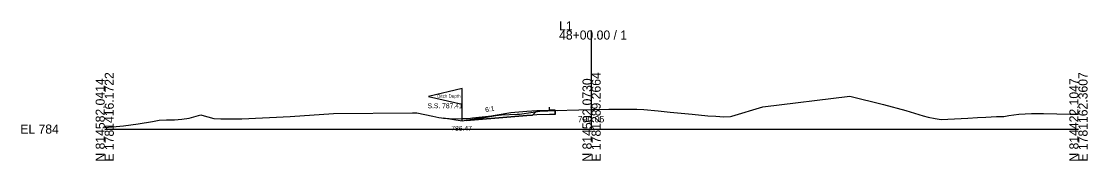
# Model space of a CAD drawing. Extents: x 5574 to 10203, y -10 to 9546.
# Drawn here: x 5574.3 to 5902.8, y 4990.3 to 5033.1 of the extents above; entities that cross this region are included whole.
import ezdxf

# ---------------------------------------------------------------- set-up
doc = ezdxf.new("R2010")
doc.units = 0
for name, color, linetype in [('Exist Cross Section Cell', 7, 'Continuous'), ('Exist XS Center Line Elevation Label', 7, 'Continuous'), ('Exist XS Ground Line', 7, 'Continuous'), ('Prop XS Ditch Slope Text', 7, 'Continuous'), ('Prop XS Ditch Standard Text', 7, 'Continuous'), ('Prop XS Dump Level', 7, 'Continuous'), ('Prop XS Earthwork Shape', 7, 'Continuous'), ('Prop XS EOT Tick Mark', 7, 'Continuous'), ('Prop XS Finish Grade', 7, 'Continuous'), ('Prop XS Finish Grade Earthwork', 7, 'Continuous'), ('Prop XS Finish Grade Paved Shoulder', 7, 'Continuous'), ('Prop XS Finish Grade Pavement', 7, 'Continuous'), ('Prop XS Hydro Typical Ditch Data', 7, 'Continuous'), ('Prop XS Pvmt Edge Slope', 7, 'Continuous'), ('Prop XS SS Elevation Text', 7, 'Continuous'), ('Prop XS Subgrade Earthwork', 7, 'Continuous'), ('Scratch_Level_3', 7, 'Continuous'), ('Scratch_Level_6', 7, 'Continuous')]:
    doc.layers.add(name, color=color, linetype=linetype)

msp = doc.modelspace()

# ---------------------------------------------------------------- linework, layer by layer
at = {"layer": 'Exist Cross Section Cell'}
for p, q in [((5750, 5000), (5750, 5030.32)), ((5600, 5000), (5750, 5000)), ((5750, 5000), (5900, 5000))]:
    msp.add_line(p, q, dxfattribs=at)
at = {"layer": 'Exist XS Ground Line'}
for p, q in [((5802.73, 5006.82), (5829.61, 5010.11)), ((5829.61, 5010.11), (5839.91, 5007.6)), ((5839.91, 5007.6), (5846.85, 5005.73)), ((5626.05, 5003.38), (5629.61, 5004.37)), ((5629.61, 5004.37), (5629.94, 5004.32)), ((5629.94, 5004.32), (5633.58, 5003.26)), ((5642.23, 5003.14), (5657.09, 5003.9)), ((5657.09, 5003.9), (5670.49, 5004.75)), ((5670.49, 5004.75), (5694.79, 5004.96)), ((5694.79, 5004.96), (5696.12, 5004.99)), ((5696.12, 5004.99), (5701.04, 5003.94)), ((5701.04, 5003.94), (5702.97, 5003.52)), ((5713.27, 5003.42), (5722.27, 5004.39)), ((5722.27, 5004.39), (5727.12, 5004.6)), ((5727.12, 5004.6), (5727.76, 5004.62)), ((5727.76, 5004.62), (5728.49, 5004.73)), ((5728.49, 5004.73), (5734.05, 5005.49)), ((5734.05, 5005.49), (5736.53, 5005.63)), ((5736.53, 5005.63), (5738.81, 5005.76)), ((5738.81, 5005.76), (5746.05, 5005.95)), ((5746.05, 5005.95), (5750, 5006.05)), ((5750, 5006.05), (5750.76, 5006.07)), ((5750.76, 5006.07), (5755.32, 5006.11)), ((5755.32, 5006.11), (5761.96, 5006.17)), ((5761.96, 5006.17), (5763.89, 5006.1)), ((5763.89, 5006.1), (5766.05, 5006.02)), ((5766.05, 5006.02), (5770.5, 5005.59)), ((5770.5, 5005.59), (5774.25, 5005.25)), ((5774.25, 5005.25), (5780.97, 5004.59)), ((5780.97, 5004.59), (5785.82, 5004.12)), ((5785.82, 5004.12), (5788.26, 5003.94)), ((5788.26, 5003.94), (5790.79, 5003.77)), ((5790.79, 5003.77), (5792.84, 5003.89)), ((5792.84, 5003.89), (5793.24, 5004)), ((5793.24, 5004), (5802.73, 5006.82)), ((5846.85, 5005.73), (5852.15, 5004.05)), ((5852.15, 5004.05), (5853.7, 5003.7)), ((5853.7, 5003.7), (5855.85, 5003.24)), ((5868.91, 5003.54), (5871.47, 5003.71)), ((5871.47, 5003.71), (5874.76, 5003.88)), ((5874.76, 5003.88), (5877.01, 5003.88)), ((5877.01, 5003.88), (5878.51, 5004.13)), ((5878.51, 5004.13), (5881.64, 5004.61)), ((5881.64, 5004.61), (5885.5, 5004.78)), ((5885.5, 5004.78), (5886.56, 5004.83)), ((5886.56, 5004.83), (5889.18, 5004.78)), ((5889.18, 5004.78), (5897.43, 5004.63)), ((5897.43, 5004.63), (5900, 5004.58)), ((5600, 5000.53), (5605.83, 5001.05)), ((5605.83, 5001.05), (5610.3, 5001.64)), ((5610.3, 5001.64), (5614.68, 5002.36)), ((5614.68, 5002.36), (5616.77, 5002.73)), ((5616.77, 5002.73), (5619.01, 5002.88)), ((5619.01, 5002.88), (5619.32, 5002.89)), ((5619.32, 5002.89), (5621.46, 5002.89)), ((5621.46, 5002.89), (5623.75, 5003.07)), ((5623.75, 5003.07), (5626.05, 5003.38)), ((5633.58, 5003.26), (5635.81, 5003.11)), ((5635.81, 5003.11), (5642.23, 5003.14)), ((5702.97, 5003.52), (5703.79, 5003.45)), ((5703.79, 5003.45), (5704.67, 5003.4)), ((5704.67, 5003.4), (5707.54, 5003.17)), ((5707.54, 5003.17), (5710.02, 5003.24)), ((5710.02, 5003.24), (5711.87, 5003.28)), ((5711.87, 5003.28), (5712.7, 5003.34)), ((5712.7, 5003.34), (5713.27, 5003.42)), ((5855.85, 5003.24), (5857.71, 5002.98)), ((5857.71, 5002.98), (5865.88, 5003.36)), ((5865.88, 5003.36), (5868.91, 5003.54))]:
    msp.add_line(p, q, dxfattribs=at)
at = {"layer": 'Prop XS Dump Level'}
for p, q in [((5710.08, 5012.47), (5699.78, 5010.07)), ((5710.08, 5007.67), (5710.08, 5012.47)), ((5699.78, 5010.07), (5710.08, 5007.67)), ((5710.08, 5002.47), (5710.08, 5007.67)), ((5738.82, 5005.83), (5737.08, 5005.79)), ((5738.82, 5005.83), (5737.08, 5005.79))]:
    msp.add_line(p, q, dxfattribs=at)
at = {"layer": 'Prop XS Earthwork Shape'}
msp.add_lwpolyline([(5704.39, 5003.41), (5704.67, 5003.4), (5707.54, 5003.17), (5710.02, 5003.24), (5711.87, 5003.28), (5712.7, 5003.34), (5713.27, 5003.42), (5722.27, 5004.39), (5727.12, 5004.6), (5727.76, 5004.62), (5728.49, 5004.73), (5734.05, 5005.49), (5736.53, 5005.63), (5738.81, 5005.76), (5738.81, 5004.51), (5737.08, 5004.46), (5733.08, 5004.36), (5731.79, 5004.32), (5730.08, 5004.18), (5725.08, 5003.78), (5711.44, 5002.69), (5710.08, 5002.47)], close=True, dxfattribs=at)
at = {"layer": 'Prop XS EOT Tick Mark'}
msp.add_line((5737.08, 5005.71), (5737.08, 5006.71), dxfattribs=at)
at = {"layer": 'Prop XS Finish Grade'}
for p, q in [((5725.08, 5004.97), (5711.44, 5002.69)), ((5730.08, 5005.37), (5725.08, 5004.97)), ((5733.08, 5005.61), (5730.08, 5005.37))]:
    msp.add_line(p, q, dxfattribs=at)
at = {"layer": 'Prop XS Finish Grade Earthwork'}
for p, q in [((5710.08, 5002.47), (5704.39, 5003.41)), ((5711.44, 5002.69), (5710.08, 5002.47))]:
    msp.add_line(p, q, dxfattribs=at)
at = {"layer": 'Prop XS Finish Grade Paved Shoulder'}
msp.add_line((5737.08, 5005.71), (5733.08, 5005.61), dxfattribs=at)
at = {"layer": 'Prop XS Finish Grade Pavement'}
msp.add_line((5738.81, 5005.76), (5737.08, 5005.71), dxfattribs=at)
at = {"layer": 'Prop XS Hydro Typical Ditch Data'}
for p, q in [((5725.08, 5004.97), (5710.08, 5002.47)), ((5710.08, 5002.47), (5704.39, 5003.41))]:
    msp.add_line(p, q, dxfattribs=at)
at = {"layer": 'Prop XS Pvmt Edge Slope'}
msp.add_line((5733.08, 5005.61), (5731.79, 5004.32), dxfattribs=at)
at = {"layer": 'Prop XS Subgrade Earthwork'}
for p, q in [((5725.08, 5003.78), (5711.44, 5002.69)), ((5730.08, 5004.18), (5725.08, 5003.78)), ((5731.79, 5004.32), (5730.08, 5004.18)), ((5733.08, 5004.36), (5731.79, 5004.32)), ((5737.08, 5004.46), (5733.08, 5004.36)), ((5738.81, 5004.51), (5737.08, 5004.46)), ((5738.81, 5004.51), (5738.81, 5005.76))]:
    msp.add_line(p, q, dxfattribs=at)
at = {"layer": 'Scratch_Level_3'}
for p, q in [((5725.08, 5004.97), (5711.44, 5002.69)), ((5711.44, 5002.69), (5725.08, 5003.78)), ((5730.08, 5005.37), (5725.08, 5004.97)), ((5725.08, 5003.78), (5730.08, 5004.18)), ((5733.08, 5005.61), (5730.08, 5005.37)), ((5730.08, 5004.18), (5731.79, 5004.32)), ((5731.79, 5004.32), (5733.08, 5005.61))]:
    msp.add_line(p, q, dxfattribs=at)
at = {"layer": 'Scratch_Level_6'}
msp.add_lwpolyline([(5720.47, 5004.2), (5722.27, 5004.39), (5727.12, 5004.6), (5727.76, 5004.62), (5728.49, 5004.73), (5734.05, 5005.49), (5736.53, 5005.63), (5738.81, 5005.76), (5738.81, 5004.51), (5737.08, 5004.46), (5733.08, 5004.36), (5731.79, 5004.32), (5730.08, 5004.18), (5725.08, 5003.78), (5711.44, 5002.69)], close=True, dxfattribs=at)

# ---------------------------------------------------------------- texts
at = {"layer": 'Exist Cross Section Cell'}
for s, p in [('L1', (5740, 5030.32)), ('48+00.00 / 1', (5740, 5027.52)), ('EL 784', (5574, 4998.6))]:
    msp.add_text(s, height=2.8, dxfattribs=at).set_placement(p)
for s, p in [('E 1781416.1722', (5602.8, 4990)), ('E 1781289.2664', (5752.8, 4990)), ('E 1781162.3607', (5902.8, 4990)), ('N 814582.0414', (5600, 4990)), ('N 814502.0730', (5750, 4990)), ('N 814422.1047', (5900, 4990))]:
    msp.add_text(s, height=2.8, rotation=90, dxfattribs=at).set_placement(p)
at = {"layer": 'Exist XS Center Line Elevation Label'}
msp.add_text('790.05', height=2, dxfattribs=at).set_placement((5745.74, 5002.05))
at = {"layer": 'Prop XS Ditch Slope Text'}
msp.add_text('6:1', height=1.5, rotation=9.4623, dxfattribs=at).set_placement((5717.33, 5005.19))
at = {"layer": 'Prop XS Ditch Standard Text'}
msp.add_text('786.47', height=1.5, dxfattribs=at).set_placement((5706.78, 4999.47))
at = {"layer": 'Prop XS Dump Level'}
for s, height, p in [('Ditch Depth', 1, (5702.42, 5009.64)), ('Case4', 0.04, (5725.08, 5004.93)), ('Eop', 0.3, (5738.81, 5005.46))]:
    msp.add_text(s, height=height, dxfattribs=at).set_placement(p)
at = {"layer": 'Prop XS SS Elevation Text'}
msp.add_text('S.S. 787.41', height=1.5, dxfattribs=at).set_placement((5699.46, 5006.41))

doc.saveas('drawing.dxf')
